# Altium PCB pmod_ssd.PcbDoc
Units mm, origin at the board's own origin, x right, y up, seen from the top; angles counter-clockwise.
Board outline 152.4 x 101.6 mm, 2 copper layers (Top Layer, Bottom Layer); 15 components, 20 nets, 66 pads, 14 vias.
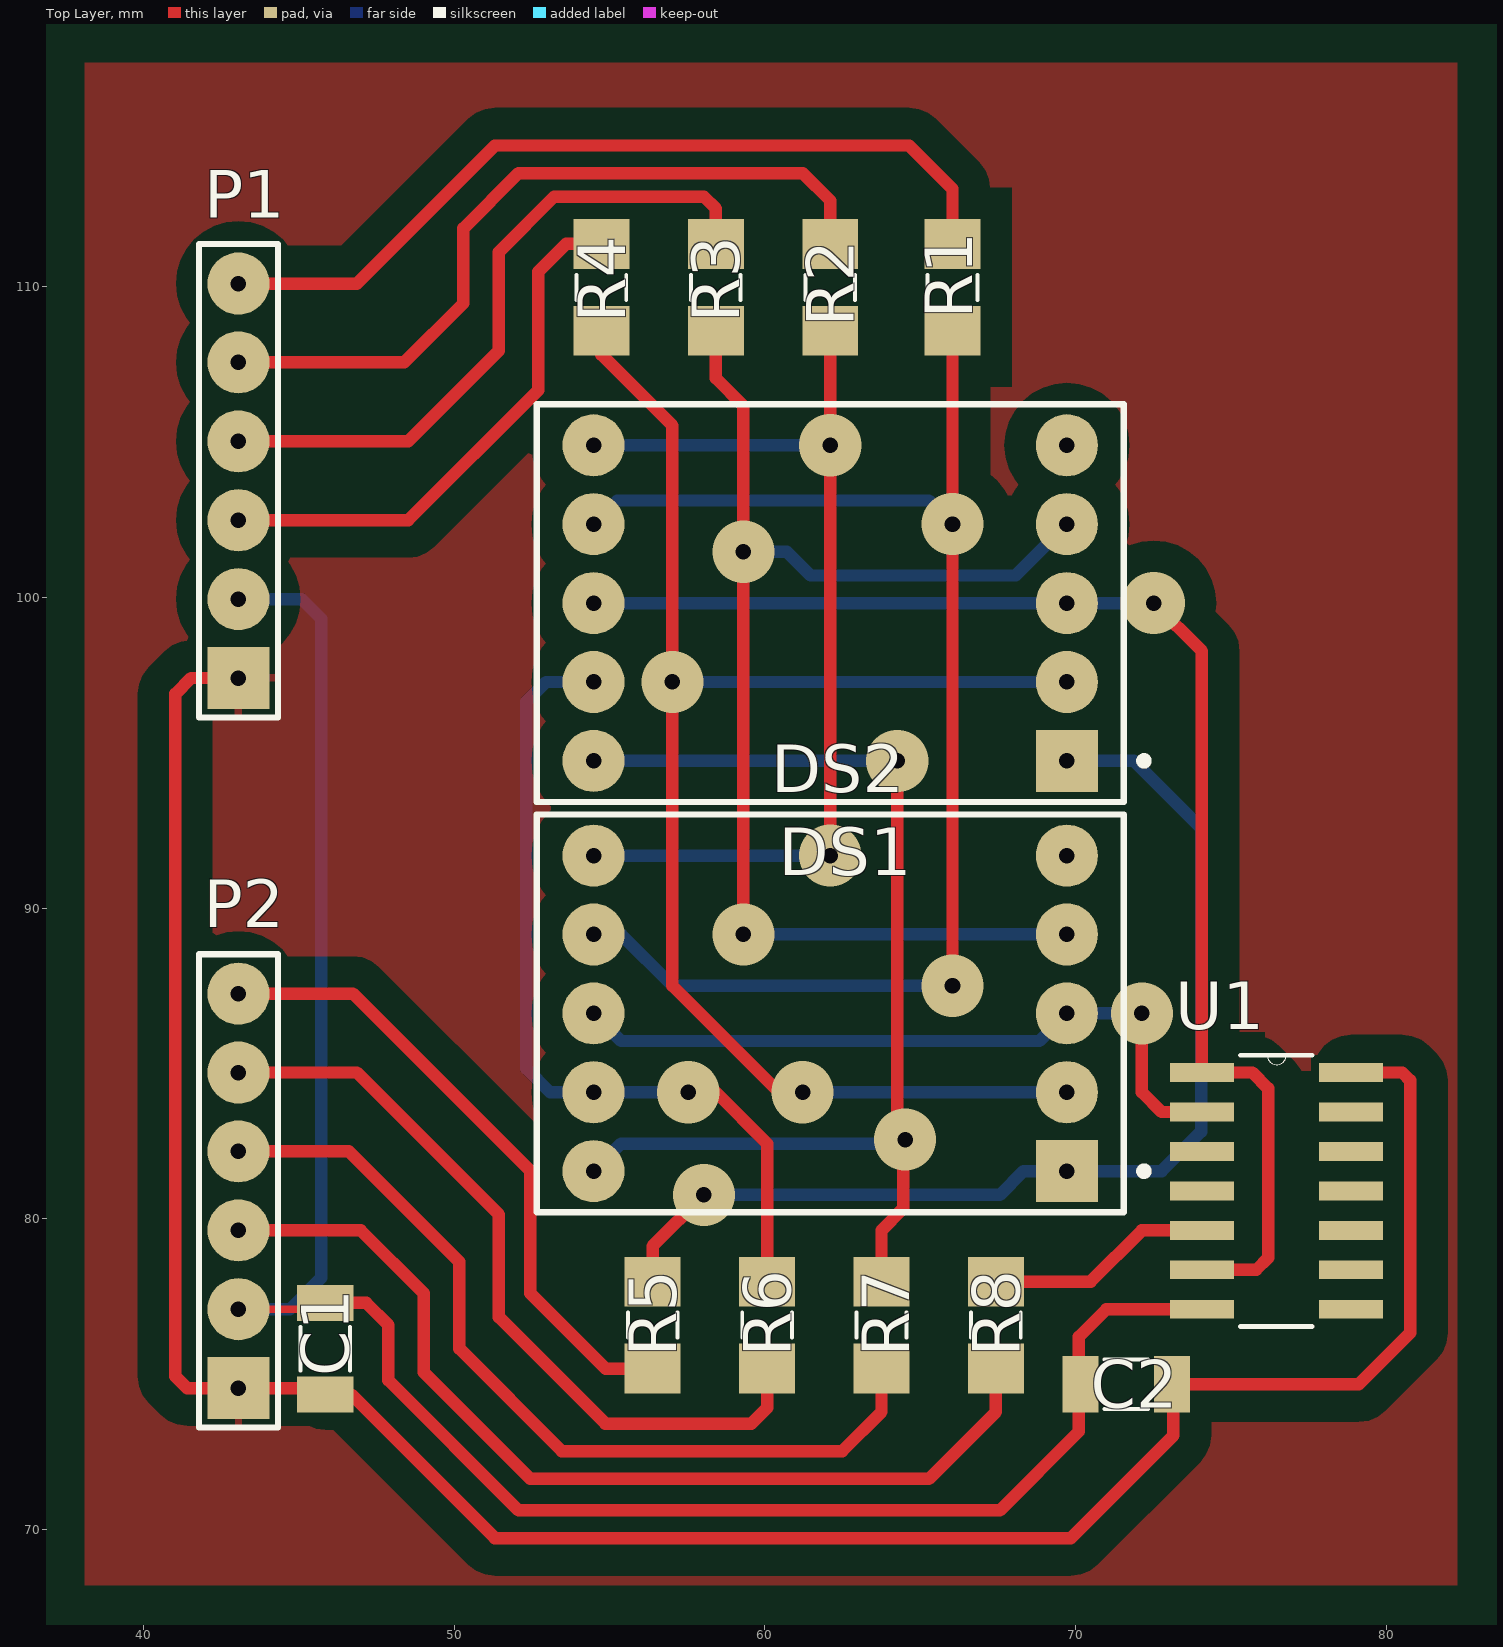
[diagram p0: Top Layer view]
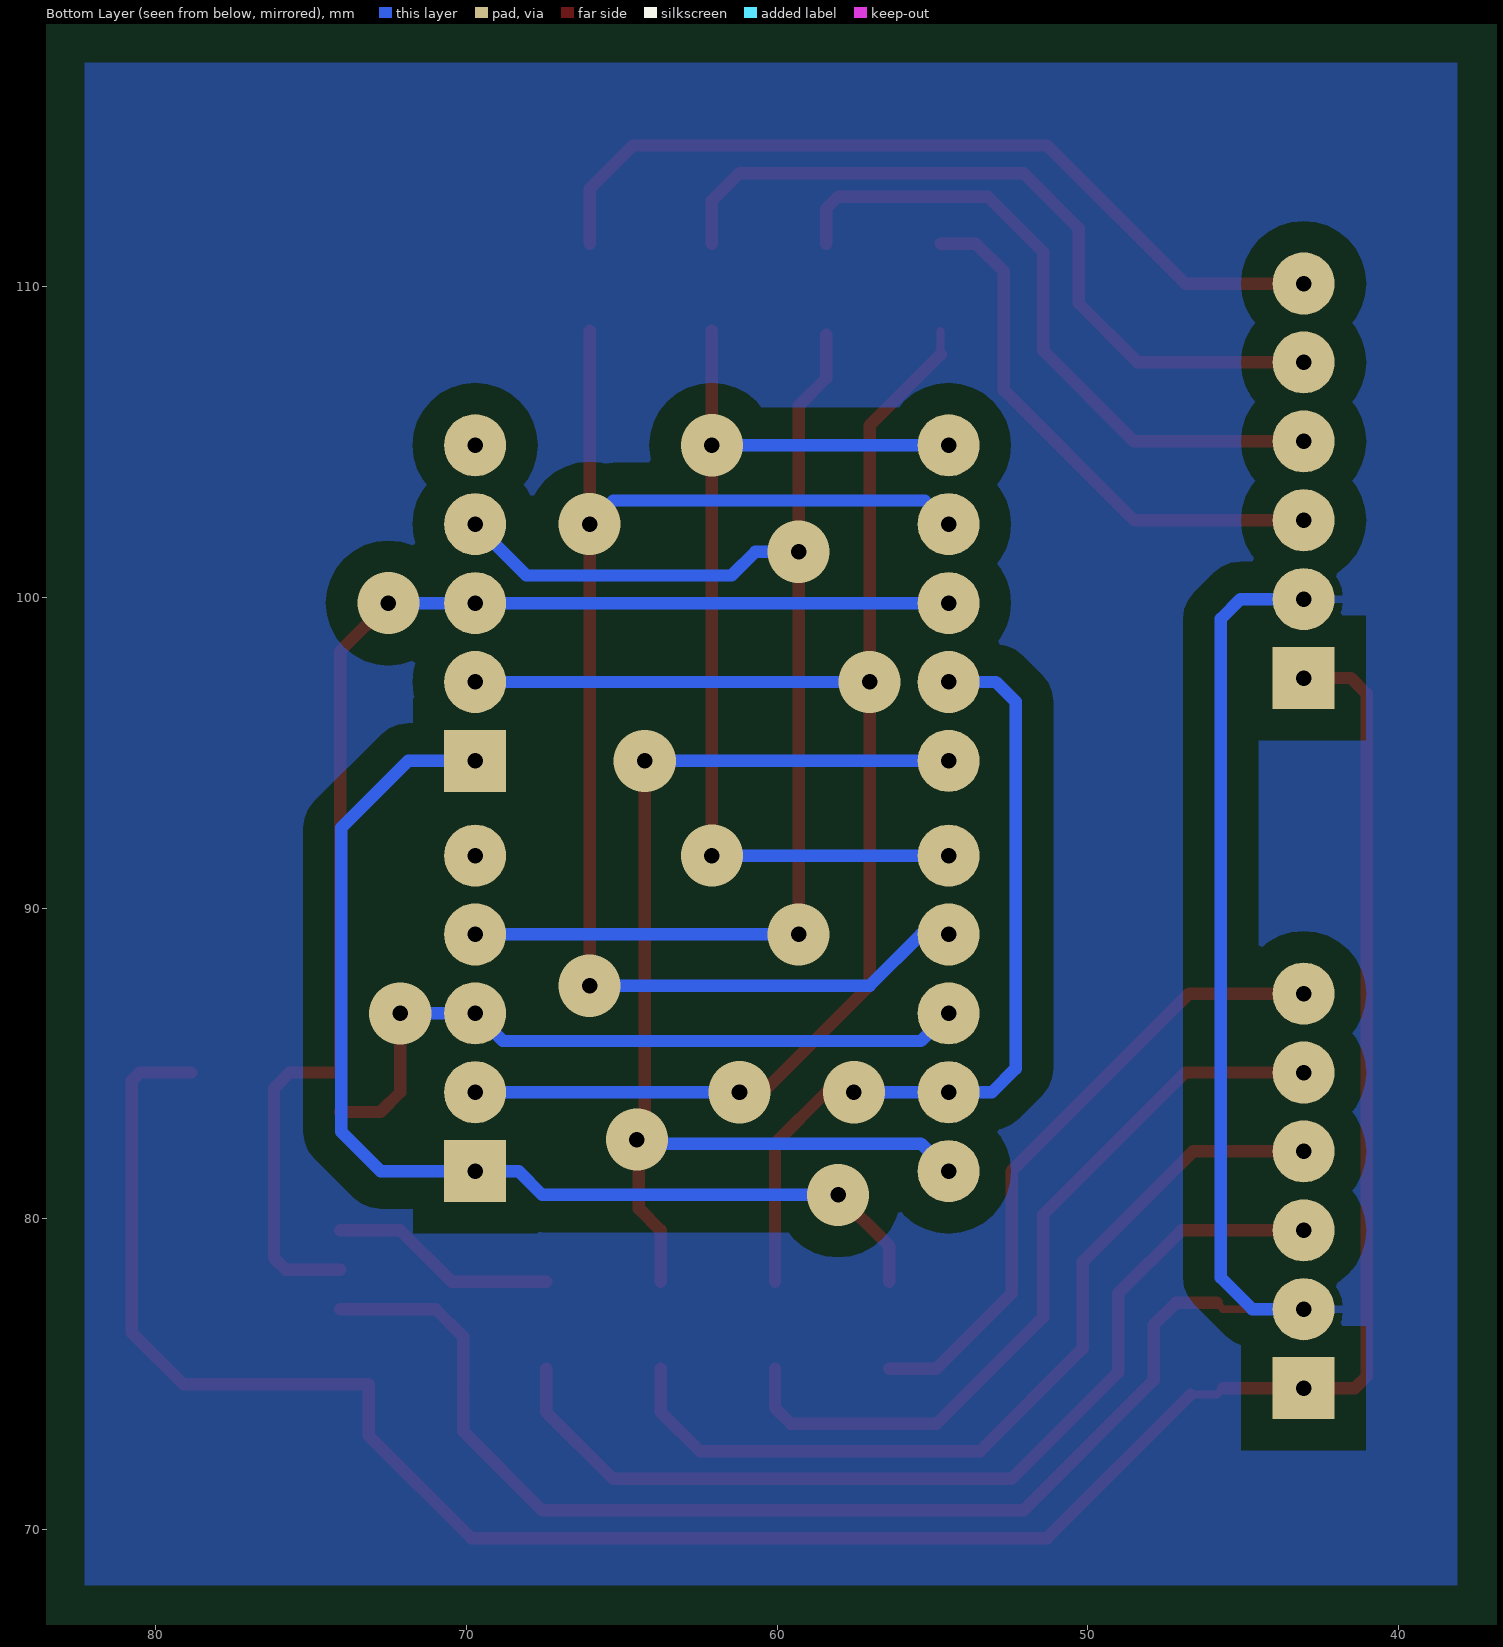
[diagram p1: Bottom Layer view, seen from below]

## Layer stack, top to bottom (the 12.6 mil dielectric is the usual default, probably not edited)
Top Solder: solder mask 0.0102, Solder Resist, Dk 3.5
Top Layer: signal copper 0.0356
Dielectric 1: dielectric 0.32, FR-4, Dk 4.8
Bottom Layer: signal copper 0.0356
Bottom Solder: solder mask 0.0102, Solder Resist, Dk 3.5

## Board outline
25.4,25.4 177.8,25.4 177.8,127 25.4,127

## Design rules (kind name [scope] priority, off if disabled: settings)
Clearance [All] p1: gap=1
PolygonConnect [All] p1: connectstyle=Relief reliefconductorwidth=0.254 reliefentries=4 polygonreliefangle="90 Angle" airgapwidth=0.254
RoutingVias [All] p1: holewidth=0.5 width=3 viastyle="Through Hole" minholewidth=0.3 minwidth=1.27 maxholewidth=0.711 maxwidth=3
SolderMaskExpansion [All] p1: expansion=0.102
UnpouredPolygon [All] p1: allowunpoured=FALSE
Width [All] p1: maxlimit=0.254 minlimit=0.254 preferedwidth=0.3
29 further rules are at their usual default settings.

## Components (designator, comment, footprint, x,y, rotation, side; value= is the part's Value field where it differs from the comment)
C1 "0.1 uF" CAPC320160X94 45.847,75.819 r90 top
C2 "1 uF" CAPC320160X94 71.628,74.676 r180 top
DS1 "Dpy Blue-CC" H 62.103,86.614 r90 top
DS2 "Dpy Blue-CC" H 62.103,99.822 r90 top
P1 "Header 6" HDR1X6 43.053,97.409 r90 top
P2 "Header 6" HDR1X6 43.053,74.549 r90 top
R1 "820R" RESC3216X70 66.04,109.985 r270 top
R2 "820R" RESC3216X70 62.103,109.985 r270 top
R3 "820R" RESC3216X70 58.42,109.985 r270 top
R4 "820R" RESC3216X70 54.737,109.985 r270 top
R5 "820R" RESC3216X70 56.388,76.578 r90 top
R6 "820R" RESC3216X70 60.071,76.578 r90 top
R7 "820R" RESC3216X70 63.754,76.578 r90 top
R8 "820R" RESC3216X70 67.437,76.578 r90 top
U1 "SN74HC14DR" SOIC127P600X175-14N 78.867,77.089 r0 top

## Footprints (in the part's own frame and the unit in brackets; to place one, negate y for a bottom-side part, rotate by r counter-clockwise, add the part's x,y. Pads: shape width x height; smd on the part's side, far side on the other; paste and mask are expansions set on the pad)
CAPC320160X94 [mm]
  rect 1.16x1.82 smd: 1(-1.475,0) 2(1.475,0)
  silkscreen extent -0.7,-0.8 0.7,0.8
H [mm] "LED, 7-Segment Display, 14.2 mm, RHD; 10 Leads; Row Space 15.24 mm; Pitch 2.54 mm"
  rect 2x2 hole 0.5: 1(-5.08,-7.62)
  round 2 hole 0.5: 2(-2.54,-7.62) 3(0,-7.62) 4(2.54,-7.62) 5(5.08,-7.62) 6(5.08,7.62) 7(2.54,7.62) 8(0,7.62) 9(-2.54,7.62) 10(-5.08,7.62)
  silkscreen extent -6.4,-10.23 6.4,9.45, body extent -6.4,-9.45 6.4,9.45, height 8.25
HDR1X6 [mm] "Connector; Header; 6 Position"
  rect 2x2 hole 0.5: 1(0,0)
  round 2 hole 0.5: 2(2.54,0) 3(5.08,0) 4(7.62,0) 5(10.16,0) 6(12.7,0)
  silkscreen extent -1.27,-1.27 13.97,1.27
RESC3216X70 [mm]
  rect 1.6x1.8 smd: 1(-1.4,0) 2(1.4,0)
  silkscreen extent -0.4,-0.8 0.4,0.8
SOIC127P600X175-14N [mil]
  rect 81x24 smd: 1(-189,300) 2(-189,250) 3(-189,200) 4(-189,150) 5(-189,100) 6(-189,50) 7(-189,0) 8(0,0) 9(0,50) 10(0,100) 11(0,150) 12(0,200) 13(0,250) 14(0,300)
  silkscreen extent -140,-22 -49,322

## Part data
C1 C2: library part 12061C683KAT2A, "1206 68 nF 100 V ±10 % Tolerance X7R Surface Mount Multilayer Ceramic Capacitor"
DS1 DS2: "14.2 mm General Purpose Blue 7-Segment Display: CC, RH DP, Gray Surface"
P1 P2: "Header, 6-Pin"
R1 R2 R3 R4 R5 R6 R7 R8: library part ERA-8AED3011V, "Res Thin Film 1206 3.01K Ohm 0.5% 1/4W ±25ppm/°C Molded SMD SMD Punched Carrier T/R"
U1: "Inverter Schmitt Trigger 6-Element CMOS 14-Pin SOIC T/R"

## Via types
v1: diameter 2, hole 0.5, Top Layer to Bottom Layer, 14 vias

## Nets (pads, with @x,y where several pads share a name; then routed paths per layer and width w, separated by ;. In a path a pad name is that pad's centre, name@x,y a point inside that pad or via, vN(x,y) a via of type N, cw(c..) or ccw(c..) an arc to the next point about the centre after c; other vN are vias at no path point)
GND: C1.2 C2.2 P1.2 P2.2 U1.7 | length 66.5
  Top Layer w0.254: P2.2 45.642,77.089 C1.2
  Top Layer w0.4: C1.2 47.166,77.294 47.879,76.581 47.879,74.803 52.07,70.612 67.564,70.612 70.104,73.152 C2.2@70.104,74.549 ; C2.2@70.104,74.676 70.104,76.2 70.993,77.089 U1.7
  Bottom Layer w0.4: P2.2 44.704,77.089 45.72,78.105 45.72,99.314 45.085,99.949 P1.2
NetDS1_1: DS1.1 DS2.1 R5.2 | length 35.3
  Top Layer w0.4: R5.2 56.388,79.121 v1(58.039,80.772)
  Bottom Layer w0.4: v1(58.039,80.772) 67.564,80.772 68.326,81.534 DS1.1 72.771,81.534 74.041,82.804 74.041,92.583 71.882,94.742 DS2.1
NetDS1_2: DS1.2 DS2.2 R4.2 | length 48.8
  Top Layer w0.254: R4.2@54.737,107.823 R4.2 ; v1@60.452,84.074 v1(61.214,84.074)
  Top Layer w0.4: R4.2@54.737,107.823 57.023,105.537 v1(57.023,97.282) 57.023,87.503 v1@60.452,84.074
  Bottom Layer w0.4: v1(57.023,97.282) DS2.2 ; v1(61.214,84.074) DS1.2
NetDS1_3: DS1.3 DS1.8 U1.2 | length 23.1
  Top Layer w0.4: v1(72.136,86.614) 72.136,84.074 72.771,83.439 U1.2
  Bottom Layer w0.4: DS1.8 55.372,85.725 68.834,85.725 DS1.3 v1(72.136,86.614)
NetDS1_4: DS1.4 DS2.4 R3.2 | length 41.5
  Top Layer w0.4: R3.2@58.42,108.458 58.42,107.061 59.309,106.172 v1(59.309,101.473) v1(59.309,89.154)
  Bottom Layer w0.4: v1(59.309,89.154) DS1.4 ; v1(59.309,101.473) 60.706,101.473 61.468,100.711 68.072,100.711 DS2.4
NetDS1_6: DS1.6 DS2.6 R2.2 | length 32.1
  Top Layer w0.4: v1(62.103,91.694) v1(62.103,104.902) R2.2
  Bottom Layer w0.4: DS1.6 v1(62.103,91.694) ; DS2.6 v1(62.103,104.902)
NetDS1_7: DS1.7 DS2.7 R1.2 | length 44.4
  Top Layer w0.4: v1(66.04,87.503) v1(66.04,102.362) R1.2
  Bottom Layer w0.4: DS1.7 55.372,89.154 57.023,87.503 v1(66.04,87.503) ; 55.245,103.124 65.278,103.124 v1(66.04,102.362)
NetDS1_9: DS1.9 DS2.9 R6.2 | length 27.4
  Top Layer w0.4: v1(57.531,84.074) 58.42,84.074 60.071,82.423 R6.2
  Bottom Layer w0.4: DS2.9 52.959,97.282 52.324,96.647 52.324,84.836 53.086,84.074 DS1.9 v1(57.531,84.074)
NetDS1_10: DS1.10 DS2.10 R7.2 | length 37.3
  Top Layer w0.254: v1@64.262,82.804 v1(64.516,82.55)
  Top Layer w0.4: R7.2 63.754,79.629 64.453,80.328 v1@64.453,82.486 ; v1@64.262,82.804 v1(64.262,94.742)
  Bottom Layer w0.254: v1@64.389,82.423 v1(64.516,82.55)
  Bottom Layer w0.4: DS1.10 55.372,82.423 v1@64.389,82.423 ; DS2.10 v1(64.262,94.742)
NetDS2_3: DS2.3 DS2.8 U1.1 U1.6 | length 43.9
  Top Layer w0.4: v1(72.517,99.822) 74.066,98.273 U1.1 75.692,84.709 76.2,84.201 76.2,78.74 75.819,78.359 U1.6
  Bottom Layer w0.4: DS2.8 DS2.3 v1(72.517,99.822)
NetP1_3: P1.3 R4.1 | length 17.6
  Top Layer w0.4: P1.3 48.514,102.489 52.705,106.68 52.705,110.49 53.6,111.385 R4.1
NetP1_4: P1.4 R3.1 | length 21.8
  Top Layer w0.4: P1.4 48.514,105.029 51.435,107.95 51.435,111.125 53.213,112.903 58.039,112.903 58.42,112.522 R3.1
NetP1_5: P1.5 R2.1 | length 24.7
  Top Layer w0.4: P1.5 48.387,107.569 50.292,109.474 50.292,111.887 52.07,113.665 61.214,113.665 62.103,112.776 R2.1
NetP1_6: P1.6 R1.1 | length 27.2
  Top Layer w0.4: P1.6 46.863,110.109 51.308,114.554 64.643,114.554 66.04,113.157 R1.1
NetP2_3: P2.3 R8.1 | length 31.5
  Top Layer w0.4: P2.3 46.99,79.629 49.022,77.597 49.022,75.057 52.451,71.628 65.278,71.628 67.437,73.787 R8.1
NetP2_4: P2.4 R7.1 | length 28.3
  Top Layer w0.4: P2.4 46.609,82.169 50.165,78.613 50.165,75.819 53.467,72.517 62.484,72.517 63.754,73.787 R7.1
NetP2_5: P2.5 R6.1 | length 25.1
  Top Layer w0.4: P2.5 46.863,84.709 51.435,80.137 51.435,76.835 54.864,73.406 59.563,73.406 60.071,73.914 R6.1
NetP2_6: P2.6 R5.1 | length 20.6
  Top Layer w0.4: P2.6 46.736,87.249 52.451,81.534 52.451,77.597 54.87,75.178 R5.1
NetR8_2: R8.2 U1.5 | length 7.3
  Top Layer w0.4: R8.2 70.485,77.978 72.136,79.629 U1.5
VCC: C1.1 C2.1 P1.1 P2.1 U1.14 | length 80
  Top Layer w0.254: C1.1@45.642,74.549 C1.1 C1.1@46.687,74.344
  Top Layer w0.4: P1.1 41.529,97.409 41.021,96.901 41.021,74.93 41.402,74.549 P2.1 C1.1@45.642,74.549 ; C1.1@46.687,74.344 51.308,69.723 69.85,69.723 73.152,73.025 73.152,74.676 79.121,74.676 80.772,76.327 80.772,84.455 80.518,84.709 U1.14
pads on no net: DS1.5 DS2.5 U1.3 U1.4 U1.8 U1.9 U1.10 U1.11 U1.12 U1.13

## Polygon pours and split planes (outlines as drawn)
GND on Bottom Layer "Bottom Layer-No Net" (solid, remove dead copper, pour order 2): 38.1,117.221 82.296,117.221 82.296,68.199 38.1,68.199
VCC on Top Layer "Bottom Layer-No Net" (solid, remove dead copper, pour order 4): 38.1,117.221 82.296,117.221 82.296,68.199 38.1,68.199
